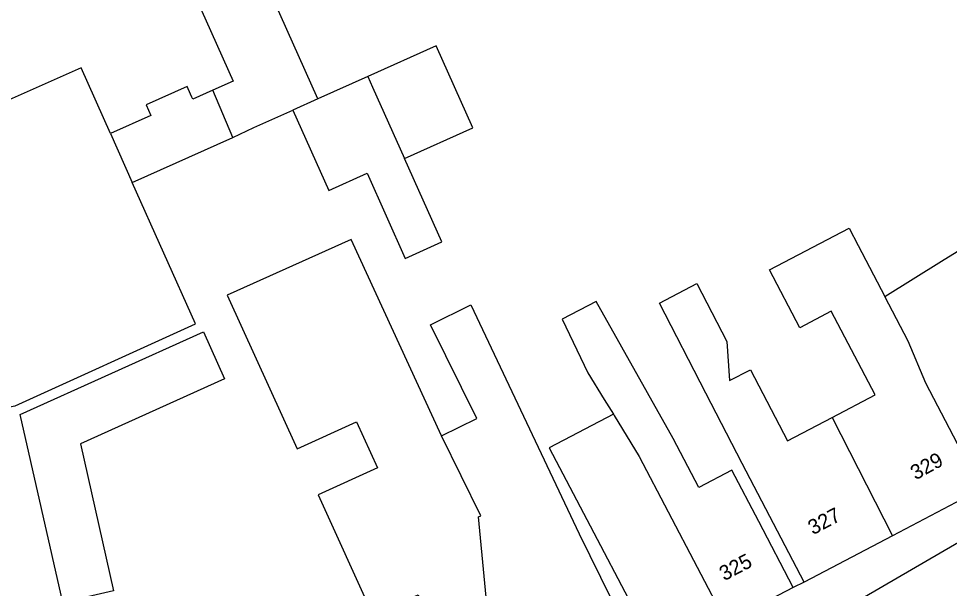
# Model space of a CAD drawing. Extents: x 163010 to 163853, y 382793 to 383982.
# Drawn here: x 163356.6 to 163419.3, y 383661.5 to 383699.9 of the extents above; entities that cross this region are included whole.
import ezdxf

# ---------------------------------------------------------------- set-up
doc = ezdxf.new("R2010")
doc.units = 0
for name, color, linetype in [('IMGEO_Fietspad_open', 7, 'Continuous'), ('IMGEO_Pand', 7, 'Continuous'), ('IMGEO_Pand_nummerreeks', 7, 'Continuous'), ('IMGEO_Voetpad_open', 7, 'Continuous')]:
    doc.layers.add(name, color=color, linetype=linetype)

msp = doc.modelspace()

# ---------------------------------------------------------------- linework, layer by layer
at = {"layer": 'IMGEO_Fietspad_open'}
msp.add_lwpolyline([(163405.856, 383656.462), (163491.247, 383706.08), (163500, 383711.017), (163512.387, 383717.643), (163569.257, 383747.053), (163574.956, 383750), (163654.435, 383791.132)], dxfattribs=at)
at = {"layer": 'IMGEO_Pand'}
for points in [[(163376.726, 383694.472), (163371.687, 383705.734), (163367.375, 383703.805), (163371.016, 383695.668), (163369.652, 383695.058)], [(163382.571, 383690.456), (163387.184, 383692.519), (163384.712, 383698.045), (163380.099, 383695.981)], [(163362.749, 383692.144), (163360.772, 383696.562), (163355.302, 383694.14)], [(163380.099, 383695.981), (163376.726, 383694.472)], [(163380.099, 383695.981), (163380.257, 383695.628), (163380.417, 383695.271), (163382.571, 383690.456)], [(163369.652, 383695.058), (163368.298, 383694.453), (163368.238, 383694.589), (163368.146, 383694.793), (163367.914, 383695.311), (163365.15, 383694.074), (163365.469, 383693.361), (163362.749, 383692.144)], [(163370.999, 383691.871), (163369.652, 383695.058)], [(163376.726, 383694.472), (163375.045, 383693.72)], [(163370.999, 383691.871), (163372.414, 383692.543), (163375.045, 383693.72)], [(163375.045, 383693.72), (163377.465, 383688.31), (163380.048, 383689.465), (163382.613, 383683.732), (163385.085, 383684.838), (163382.571, 383690.456)], [(163362.749, 383692.144), (163364.227, 383688.841)], [(163364.227, 383688.841), (163370.999, 383691.871)], [(163347.88, 383690.853), (163347.227, 383690.564), (163350.923, 383672.865), (163356.341, 383673.807), (163368.479, 383679.336), (163364.227, 383688.841)], [(163411.405, 383673.022), (163414.293, 383674.535), (163411.336, 383680.176), (163409.208, 383679.061), (163407.167, 383682.955), (163412.538, 383685.769), (163413.155, 383684.591), (163414.948, 383681.17)], [(163385.061, 383671.774), (163378.981, 383685.01), (163370.62, 383681.251), (163375.339, 383670.901), (163379.342, 383672.727), (163380.753, 383669.632), (163376.75, 383667.807), (163380.447, 383659.7), (163383.495, 383661.09), (163385.093, 383657.585), (163382.01, 383656.179), (163382.026, 383656.143), (163385.202, 383649.625)], [(163414.948, 383681.17), (163418.762, 383683.538), (163421.633, 383685.32)], [(163409.507, 383661.933), (163407.186, 383666.362), (163405.326, 383669.911), (163402.875, 383674.668), (163399.758, 383680.718), (163402.285, 383682.036), (163404.295, 383678.134), (163404.48, 383675.505), (163405.881, 383676.236), (163408.393, 383671.443), (163411.405, 383673.022)], [(163408.768, 383661.582), (163406.447, 383666.011), (163404.631, 383669.475), (163402.412, 383668.313), (163400.686, 383671.607), (163395.485, 383680.83), (163393.203, 383679.634), (163394.931, 383676.026), (163396.036, 383674.232), (163396.649, 383673.237)], [(163421.442, 383668.187), (163417.702, 383675.323), (163416.524, 383678.162), (163414.948, 383681.17)], [(163385.061, 383671.774), (163387.44, 383672.955), (163384.316, 383679.252), (163387.036, 383680.602), (163394.334, 383665.181), (163396.495, 383660.81), (163398.717, 383656.331)], [(163362.965, 383661.339), (163359.534, 383660.566), (163356.679, 383673.22), (163369.031, 383678.78), (163370.449, 383675.631), (163360.728, 383671.254), (163362.965, 383661.339)], [(163396.649, 383673.237), (163392.328, 383670.971), (163395.554, 383664.817), (163397.411, 383661.275), (163399.732, 383656.846)], [(163396.649, 383673.237), (163396.702, 383673.15), (163398.388, 383670.403), (163404.249, 383659.214)], [(163411.405, 383673.022), (163415.469, 383665.058)], [(163391.293, 383652.647), (163388.375, 383657.866), (163387.567, 383666.321), (163387.727, 383666.4), (163385.061, 383671.774)], [(163421.442, 383668.187), (163415.469, 383665.058)], [(163415.469, 383665.058), (163409.507, 383661.933)], [(163408.768, 383661.582), (163404.249, 383659.214)]]:
    msp.add_lwpolyline(points, dxfattribs=at)
at = {"layer": 'IMGEO_Voetpad_open'}
msp.add_lwpolyline([(163409.507, 383661.933), (163408.768, 383661.582)], dxfattribs=at)

# ---------------------------------------------------------------- texts
at = {"layer": 'IMGEO_Pand_nummerreeks'}
for s, rotation, p in [('329', 28.69946, (163417.019, 383668.779)), ('327', 27.65667, (163410.098, 383665.088)), ('325', 27.6624, (163404.118, 383661.991))]:
    msp.add_text(s, height=1, rotation=rotation, dxfattribs=at).set_placement(p)

doc.saveas('drawing.dxf')
